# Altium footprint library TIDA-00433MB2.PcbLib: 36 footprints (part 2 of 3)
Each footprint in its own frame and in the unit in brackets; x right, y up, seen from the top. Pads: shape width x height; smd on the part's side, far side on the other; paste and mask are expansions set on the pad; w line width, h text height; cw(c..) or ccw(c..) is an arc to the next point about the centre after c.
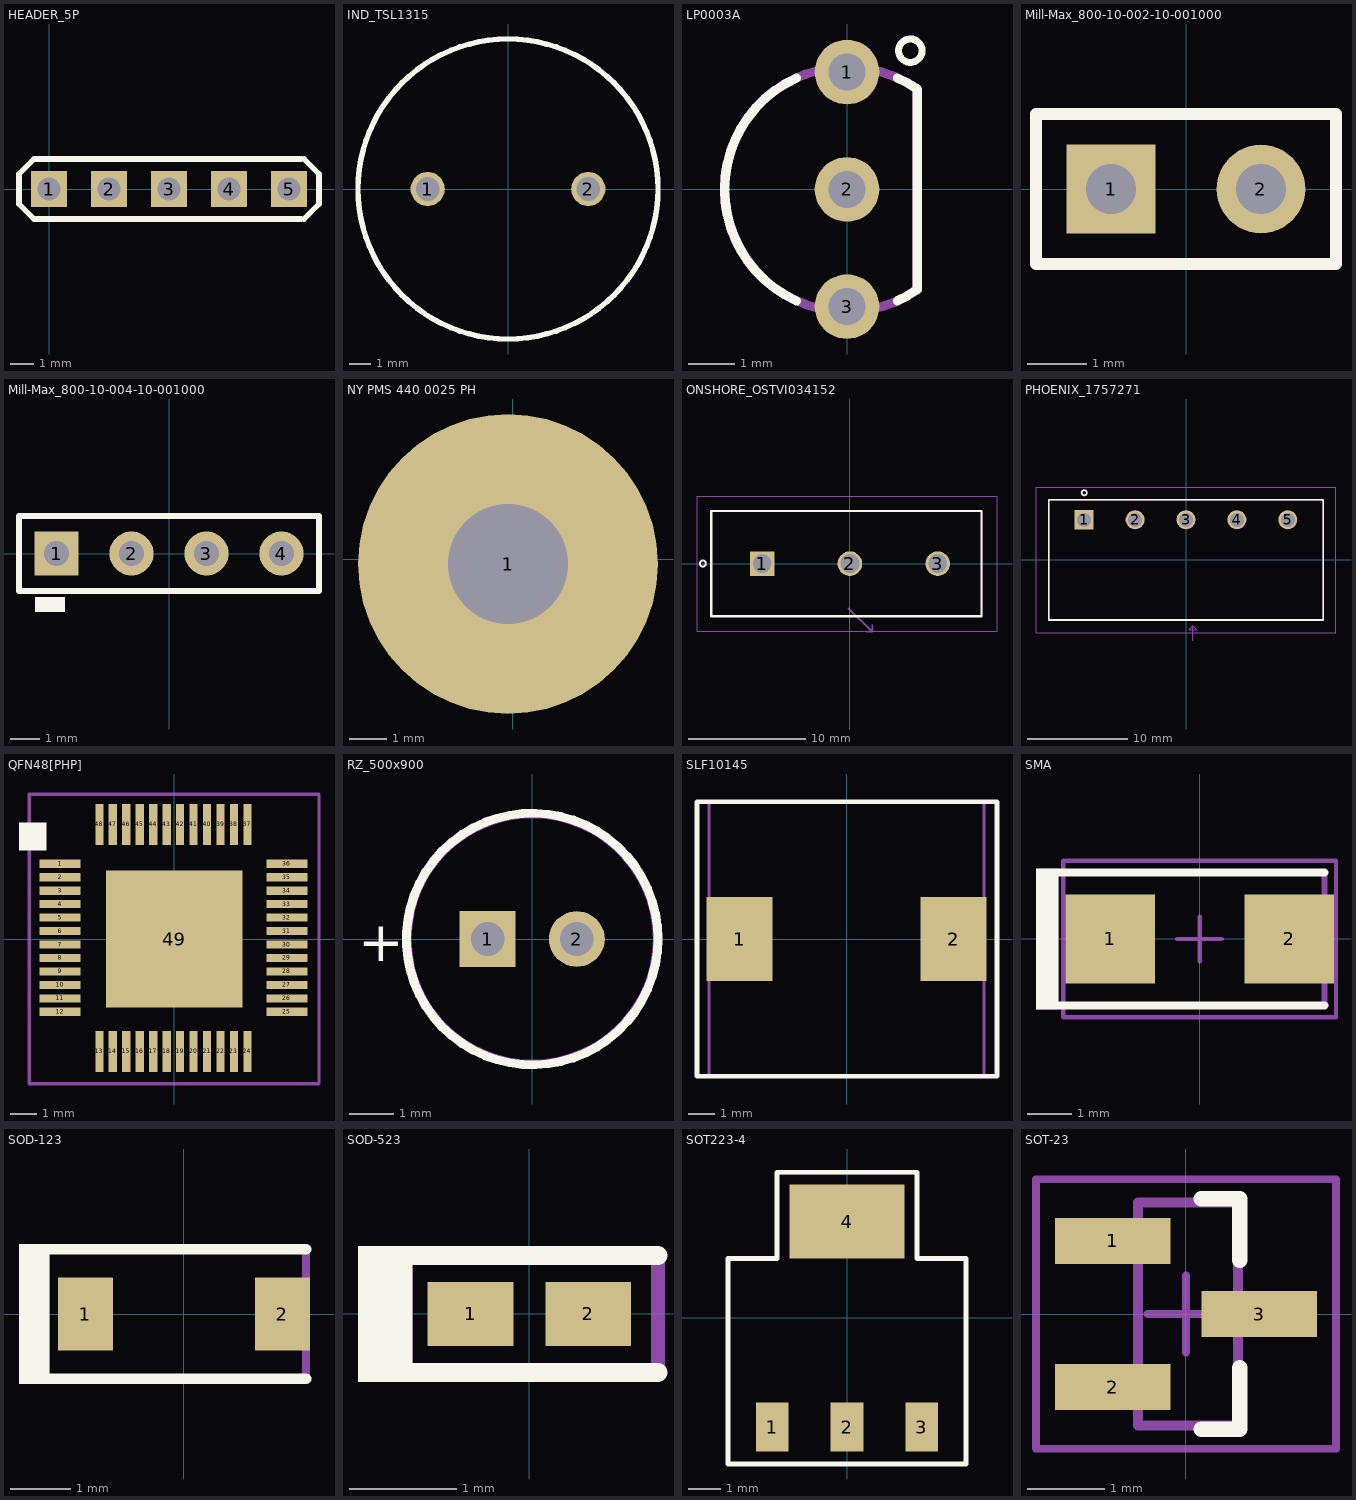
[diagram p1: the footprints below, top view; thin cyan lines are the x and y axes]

## HEADER_5P [mil]
pads (5):
  rect 60x60 hole 38: 1(0,0) 2(100,0) 3(200,0) 4(300,0) 5(400,0)
Top Overlay:
  lines w10: 420,-50 -25,-50 -50,-25 -50,25 -25,50 420,50 ; 425,-50 450,-25 450,25 425,50
Mechanical 5:
  lines w5: 420,-50 -25,-50 -50,-25 -50,25 -25,50 420,50 ; 425,-50 450,-25 450,25 425,50
  text "*" at -39,-18 h35
  text ".Designator" at 189,62 h35

## IND_TSL1315 [mm] "TDK"
height 17
pads (2):
  round 1.6 hole 1.1: 1(-3.75,0) 2(3.75,0)
Top Overlay:
  circle w0.254: c0,0 r7.006
Mechanical 5:
  circle w0.1: c0,0 r7
  text ".Designator" at -0.914,-0.61 h0.89
3D body: height 17, standoff 0, extent -7.011,-7.011 7.011,7.011
3D body: height 1, standoff -3, extent -4.147,-0.399 -3.35,0.399
3D body: height 1, standoff -3, extent 3.353,-0.399 4.15,0.399

## LP0003A [mm] "TO, Flat Index; 3 In-Line, Formed Axial Leads; Body Dia. 4.8mm; Leads 0.56 x 0.41 mm (max)"
height 9.33
pads (3):
  round 1.4 hole 0.8: 1(0,2.54) 2(0,0) 3(0,-2.54)
Top Overlay:
  circle w0.152: c1.371,3.003 r0.254
  lines w0.2: -1.092,-2.415 cw(c0,0) -1.092,2.415 ; 1.092,-2.415 ccw(c0,0) 1.52,-2.171 1.52,2.171 ccw(c0,0) 1.092,2.415
Mechanical 5:
  lines w0.2: 1.52,-2.171 cw(c0,0) 1.52,2.171 1.52,-2.171
  text ".Designator" at -1.27,-0.33 h0.89
Mechanical 15:
  lines w0.1: -0.5,0 0.5,0 ; 0,-0.5 0,0.5
3D body: height 9.33, standoff 3.99, extent -2.659,-2.659 1.523,2.659

## Mill-Max_800-10-002-10-001000 [mm] "Mill-Max"
height 8.128
pads (2):
  rect 1.5x1.5 hole 0.85: 1(-1.27,0)
  round 1.5 hole 0.85: 2(1.27,0)
Top Overlay:
  lines w0.203: -2.54,-1.27 2.54,-1.27 2.54,1.27 -2.54,1.27 -2.54,-1.27
Mechanical 5:
  lines w0.102: -2.54,-1.27 -2.54,1.27 2.54,1.27 2.54,-1.27 -2.54,-1.27
  text ".Designator" at 0.762,-0.152 h0.89
3D body: height 3.17, standoff 0, extent -2.539,-1.269 2.539,1.269
3D body: height 8.13, standoff 0, extent 0.892,-0.38 1.651,0.38
3D body: height 8.13, standoff 0, extent -1.648,-0.38 -0.889,0.38
3D body: height 0.81, standoff -3, extent 0.968,-0.304 1.575,0.304
3D body: height 0.81, standoff -3, extent -1.572,-0.304 -0.965,0.304

## Mill-Max_800-10-004-10-001000 [mm] "Mill-Max"
height 8.128
pads (4):
  rect 1.5x1.5 hole 0.85: 1(-3.81,0)
  round 1.5 hole 0.85: 2(-1.27,0) 3(1.27,0) 4(3.81,0)
Top Overlay:
  rectangle: -4.547,-1.981 -3.531,-1.473
  lines w0.203: -5.08,-1.27 5.08,-1.27 5.08,1.27 -5.08,1.27 -5.08,-1.27
Mechanical 5:
  lines w0.102: -5.08,-1.27 -5.08,1.27 5.08,1.27 5.08,-1.27 -5.08,-1.27
  text ".Designator" at -0.914,0 h0.89
3D body: height 3.17, standoff 0, extent -5.079,-1.269 5.079,1.269
3D body: height 8.13, standoff 0, extent 3.432,-0.38 4.191,0.38
3D body: height 8.13, standoff 0, extent 0.892,-0.38 1.651,0.38
3D body: height 8.13, standoff 0, extent -1.648,-0.38 -0.889,0.38
3D body: height 8.13, standoff 0, extent -4.188,-0.38 -3.429,0.38
3D body: height 0.81, standoff -3, extent 3.508,-0.304 4.115,0.304
3D body: height 0.81, standoff -3, extent 0.968,-0.304 1.575,0.304
3D body: height 0.81, standoff -3, extent -1.572,-0.304 -0.965,0.304
3D body: height 0.81, standoff -3, extent -4.112,-0.304 -3.505,0.304

## NY PMS 440 0025 PH [mm] "4-40 nylon screw and mounting hole"
height 1.905
pads (1):
  round 8 hole 3.2: 1(-0.127,-0.127)
Mechanical 5:
  circle w0.127: c-0.127,-0.127 r3.789
  text ".Designator" at -1.524,-0.508 h0.89
3D body: height 2.69, standoff -8.74, extent -3.302,-3.3 3.296,3.3

## ONSHORE_OSTVI034152 [mm] "TERMINAL BLOCK, 7.5MM PITCH,THRU-3PINS"
height 13.5
pads (3):
  rect 2.1x2.1 / inner round 2.1 / far side rect 2.1x2.1 hole 1.6: 1(-7.5,0)
  round 2.1 hole 1.6: 2(0,0) 3(7.5,0)
Top Overlay:
  circle w0.152: c-12.572,0 r0.254
  lines w0.178: -11.85,-4.5 11.25,-4.5 11.25,4.5 -11.85,4.5 -11.85,-4.5
Bottom Overlay:
  lines w0.178: -11.85,-3.2 -11.85,-2.058 ; -11.85,-1.524 -11.85,-0.382 ; -11.85,0.254 -11.85,1.396 ; -11.85,1.905 -11.85,3.047 ; -11.045,-4.5 -9.903,-4.5 ; -10.717,4.5 -9.575,4.5 ; -9.14,-4.5 -7.998,-4.5 ; -8.812,4.5 -7.67,4.5 ; -7.235,-4.5 -6.093,-4.5 ; -6.907,4.5 -5.765,4.5 ; -5.33,-4.5 -4.188,-4.5 ; -5.002,4.5 -3.86,4.5 ; -3.479,-4.5 -2.337,-4.5 ; -3.097,4.5 -1.955,4.5 ; -1.828,-4.5 -0.686,-4.5 ; -1.192,4.5 -0.05,4.5 ; -0.05,-4.5 1.092,-4.5 ; 0.586,4.5 1.728,4.5 ; 1.855,-4.5 2.997,-4.5 ; 2.237,4.5 3.379,4.5 ; 3.76,-4.5 4.902,-4.5 ; 4.088,4.5 5.23,4.5 ; 5.665,-4.5 6.807,-4.5 ; 5.939,4.5 7.081,4.5 ; 7.57,-4.5 8.712,-4.5 ; 7.72,4.5 8.862,4.5 ; 9.475,-4.5 10.617,-4.5 ; 9.571,4.5 10.713,4.5 ; 11.25,-2.947 11.25,-1.805 ; 11.25,-1.296 11.25,-0.154 ; 11.25,0.482 11.25,1.624 ; 11.25,2.158 11.25,3.3
Mechanical 5:
  circle w0.127: c-12.572,0 r0.279
  lines w0.127: -11.85,-4.5 -11.85,4.5 11.25,4.5 11.25,-4.5 -11.85,-4.5
  text ".Designator" at 11.938,1.092 h0.89
Mechanical 15:
  lines w0.05: -13.07,-5.77 12.57,-5.77 12.57,5.77 -13.07,5.77 -13.07,-5.77
Mechanical 16:
  lines w0.127: -0.127,-3.81 1.905,-5.842 ; 1.397,-5.842 1.905,-5.842 ; 1.905,-5.207 1.905,-5.842
Mechanical 17:
  text "LEAD LENGTH: 3.50MM" at -8.382,2.413 h0.89
  text "MATING SIDE" at -3.937,-7.239 h0.89
3D body: height 13.5, standoff 0, extent -11.8,-4.5 11.3,4.5

## PHOENIX_1757271 [mm] "TERM BLOCK, HDR, 5POS, R/A, 5.08MM, TH"
height 8.6
pads (5):
  rect 1.9x1.9 / inner round 1.9 / far side rect 1.9x1.9 hole 1.4: 1(-10.16,4)
  round 1.9 hole 1.4: 2(-5.08,4) 3(0,4) 4(5.08,4) 5(10.16,4)
Top Overlay:
  circle w0.152: c-10.16,6.692 r0.254
  lines w0.178: -13.7,-6 -13.7,6 13.7,6 13.7,-6 -13.7,-6
Bottom Overlay:
  lines w0.178: -13.7,-4.676 -13.7,-3.025 ; -13.7,-1.676 -13.7,-0.025 ; -13.7,1.324 -13.7,2.975 ; -13.7,4.349 -13.7,6 ; -12.649,6 -10.897,6 ; -11.275,-6 -9.522,-6 ; -9.598,6 -7.846,6 ; -8.275,-6 -6.522,-6 ; -6.598,6 -4.846,6 ; -5.275,-6 -3.522,-6 ; -3.598,6 -1.846,6 ; -2.275,-6 -0.522,-6 ; -0.598,6 1.154,6 ; 0.751,-6 2.503,-6 ; 2.919,6 4.672,6 ; 4.354,-6 6.107,-6 ; 5.919,6 7.672,6 ; 7.354,-6 9.107,-6 ; 8.919,6 10.672,6 ; 10.354,-6 12.107,-6 ; 13.7,-6 13.7,-4.467 ; 13.7,-3.067 13.7,-1.467 ; 13.7,-0.067 13.7,1.533 ; 13.7,2.933 13.7,4.533
Mechanical 5:
  circle w0.127: c-10.16,6.692 r0.279
  lines w0.127: -13.7,-6 13.7,-6 13.7,6 -13.7,6 -13.7,-6
  text ".Designator" at -14.351,3.531 h0.89
Mechanical 15:
  lines w0.05: -14.97,-7.27 -14.97,7.27 14.97,7.27 14.97,-7.27 -14.97,-7.27
Mechanical 16:
  lines w0.05: 0.693,-8.099 0.693,-6.575 ; 0.693,-6.575 1.074,-6.956 0.312,-6.956 0.693,-6.575
Mechanical 17:
  text "LEAD LENGTH: 3.50MM" at -8.555,-3.351 h0.89
  text "MATING SIDE" at -4.089,-9.658 h0.89
3D body: height 8.6, standoff 0, extent -13.703,-6.008 13.703,6.007

## QFN48[PHP] [mil]
pads (49):
  rect 60x12 smd: 1(-167,110.1) 2(-167,90.4) 3(-167,70.7) 4(-167,51) 5(-167,31.3) 6(-167,11.6) 7(-167,-8.1) 8(-167,-27.8) 9(-167,-47.5) 10(-167,-67.2) 11(-167,-86.9) 12(-167,-106.6) 25(165,-106.6) 26(165,-86.9) 27(165,-67.2) 28(165,-47.5) 29(165,-27.8) 30(165,-8.1) 31(165,11.6) 32(165,31.3) 33(165,51) 34(165,70.7) 35(165,90.4) 36(165,110.1)
  rect 12x60 smd: 13(-109.4,-164.3) 14(-89.7,-164.3) 15(-70,-164.3) 16(-50.3,-164.3) 17(-30.6,-164.3) 18(-10.9,-164.3) 19(8.8,-164.3) 20(28.5,-164.3) 21(48.2,-164.3) 22(67.9,-164.3) 23(87.6,-164.3) 24(107.3,-164.3) 37(107.3,167.7) 38(87.6,167.7) 39(67.9,167.7) 40(48.2,167.7) 41(28.5,167.7) 42(8.8,167.7) 43(-10.9,167.7) 44(-30.6,167.7) 45(-50.3,167.7) 46(-70,167.7) 47(-89.7,167.7) 48(-109.4,167.7)
  rect 200x200 smd: 49(0,0)
Top Overlay:
  region: -227,170 -227,130 -187,130 -187,170
Mechanical 5:
  lines w5: -212,-212 212,-212 212,212 -212,212 -212,-212
  text "*" at -204,124 h35
  text ".Designator" at -170,38 h35

## RZ_500x900 [mm] "NICHICON"
height 10.5
pads (2):
  rect 1.25x1.25 hole 0.75: 1(-1,0)
  round 1.25 hole 0.75: 2(1,0)
Top Overlay:
  circle w0.2: c0,0 r2.816
  text "+" at -3.9,-0.5 h0.89
Mechanical 5:
  circle w0.1: c0,0 r2.75
  text "+" at -3.9,-0.5 h0.89
  text ".Designator" at -0.457,1.6 h0.89
3D body: height 10.51, standoff -4, extent -2.728,-2.745 2.75,2.746

## SLF10145 [mm]
height 4.8
pads (2):
  rect 2.5x3.2 smd: 1(-4.05,0) 2(4.05,0)
Top Overlay:
  lines w0.178: -5.664,-5.2 -5.664,5.2 5.697,5.2 5.697,-5.2 -5.664,-5.2
Mechanical 5:
  lines w0.102: -5.207,-5.207 -5.207,5.207 5.207,5.207 5.207,-5.207 -5.207,-5.207
  text ".Designator" at -0.102,-0.838 h0.89
3D body: height 4.8, standoff 0, extent -5.2,-5.2 5.2,5.2

## SMA [mm] "Molded Diode, 2-Leads, Body 4.3x2.6mm, IPC Medium Density, based on OnSemi component dimensions and land pattern"
height 2.27
pads (2):
  rect 2x2 smd: 1(-2,0) 2(2,0)
Top Overlay:
  rectangle: -3.658,-1.575 -3.15,1.575
  lines w0.178: -3.327,-1.486 2.794,-1.486 ; -3.327,1.486 2.794,1.486
Mechanical 5:
  rectangle: -3.658,-1.575 -3.15,1.575
  lines w0.127: -3.327,-1.486 2.794,-1.486 2.794,1.486 -3.327,1.486
  text ".Designator" at -0.737,0.737 h0.89
Mechanical 15:
  lines w0.1: -0.5,0 0.5,0 ; 0,-0.5 0,0.5 ; -3.05,-1.75 3.05,-1.75 3.05,1.75 -3.05,1.75 -3.05,-1.75
3D body: height 2.42, standoff 0.02, extent -2.6,-1.3 2.6,1.3

## SOD-123 [mm] "On Semi recommended land pattern"
height 1.35
pads (2):
  rect 0.915x1.22 smd: 1(-1.637,0) 2(1.637,0)
Top Overlay:
  rectangle: -2.743,-1.168 -2.235,1.168
  lines w0.178: -2.413,-1.079 2.032,-1.079 ; -2.413,1.079 2.032,1.079
Mechanical 5:
  rectangle: -2.743,-1.168 -2.235,1.168
  lines w0.127: -2.413,-1.079 2.032,-1.079 2.032,1.079 -2.413,1.079
  text ".Designator" at -1.397,-0.33 h0.89
3D body: height 1.35, standoff 0, extent -1.932,-0.9 1.932,0.9

## SOD-523 [mm] "NXP Semiconductor recommended land pattern, nominal STEP model"
height 0.7
pads (2):
  rect 0.8x0.6 smd paste-0.05: 1(-0.55,0) 2(0.55,0)
Top Overlay:
  rectangle: -1.6,-0.635 -1.092,0.635
  lines w0.178: -1.475,-0.546 0,-0.546 1.2,-0.546 ; -1.475,0.546 0,0.546 1.2,0.546
Mechanical 5:
  rectangle: -1.6,-0.635 -1.092,0.635
  lines w0.127: -1.475,-0.546 0,-0.546 1.2,-0.546 1.2,0.546 0,0.546 -1.475,0.546
  text ".Designator" at -2.083,-0.864 h0.89
3D body: height 0.72, standoff 0.02, extent -0.8,-0.399 0.8,0.399

## SOT223-4 [mil]
pads (4):
  rect 40x60 smd: 1(-91,-133) 2(0,-133) 3(91,-133)
  rect 140x90 smd: 4(0,117)
Top Overlay:
  lines w6: -145,-178 145,-178 145,72 85,72 85,177 -85,177 -85,72 -145,72 -145,-178
Mechanical 5:
  lines w5: -145,-178 -145,72 -85,72 -85,177 85,177 85,72 145,72 145,-178 -145,-178
  text ".Designator" at -35,-50 h35

## SOT-23 [mm] "SOT23, 3-Leads, Body 2.9x1.3mm, Pitch 0.95mm, Lead Span 2.5mm, IPC Medium Density"
height 1.1
pads (3):
  rect 1.5x0.6 smd: 1(-0.95,0.95) 2(-0.95,-0.95) 3(0.95,0)
Top Overlay:
  lines w0.2: 0.2,-1.5 0.7,-1.5 0.7,-0.7 ; 0.2,1.5 0.7,1.5 0.7,0.7
Mechanical 5:
  lines w0.127: -1.16,-1.15 -1.16,-0.75 -0.625,-0.75 -0.625,0.75 -1.16,0.75 -1.16,1.15 -0.625,1.15 -0.625,1.45 0.675,1.45 0.675,0.2 1.21,0.2 1.21,-0.2 0.675,-0.2 0.675,-1.45 -0.625,-1.45 -0.625,-1.15 -1.16,-1.15
  text ".Designator" at 0.457,-1.118 h0.89
Mechanical 15:
  lines w0.1: -0.5,0 0.5,0 ; 0,-0.5 0,0.5 ; -1.95,-1.75 1.95,-1.75 1.95,1.75 -1.95,1.75 -1.95,-1.75
3D body: height 1, standoff 0, extent -1.16,-1.45 1.21,1.45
